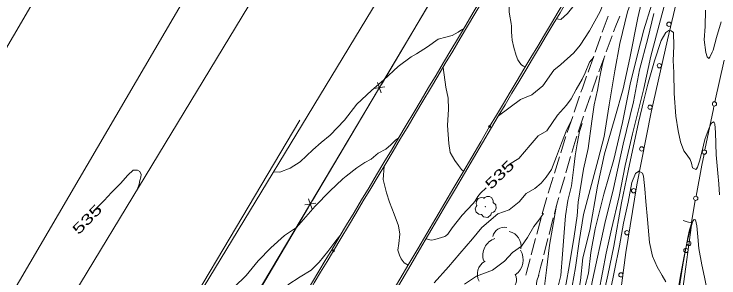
# Model space of a CAD drawing. Extents: x 2361284 to 2366480, y 6976556 to 6985346.
# Drawn here: x 2364150.7 to 2364482.3, y 6979522.2 to 6979646.3 of the extents above; entities that cross this region are included whole.
import ezdxf
from ezdxf.enums import TextEntityAlignment as Align

# ---------------------------------------------------------------- set-up
doc = ezdxf.new("R2010")
doc.units = 0
doc.header["$LTSCALE"] = 1.9
doc.header["$PDMODE"] = 32
doc.header["$PDSIZE"] = 0.95
for name, color, linetype, lineweight in [('12', 7, 'Continuous', 13), ('13', 7, 'Continuous', 13), ('16', 7, 'Continuous', 13), ('17', 7, 'Continuous', 13), ('3', 7, 'Continuous', 13), ('5', 7, 'Continuous', 13), ('6', 7, 'Continuous', 13), ('7', 7, 'Continuous', 13), ('9', 7, 'Continuous', 13)]:
    doc.layers.add(name, color=color, linetype=linetype, lineweight=lineweight)

msp = doc.modelspace()

# ---------------------------------------------------------------- linework, layer by layer
at = {"layer": '12'}
for points in [[(2364459.782, 6979662.521), (2364454.882, 6979643.634), (2364450.253, 6979626.559), (2364446.968, 6979611.337), (2364441.691, 6979589.945), (2364438.242, 6979575.132), (2364435.301, 6979560.453), (2364431.825, 6979545.209), (2364429.294, 6979533.864), (2364425.797, 6979515.601), (2364422.753, 6979501.281), (2364419.485, 6979479.998), (2364412.279, 6979443.768), (2364407.778, 6979414.374), (2364405.745, 6979397.813), (2364405.52, 6979396.2)], [(2364483.343, 6979642.624), (2364481.212, 6979635.374), (2364479.588, 6979629.428), (2364479.078, 6979628.353), (2364478.029, 6979626.133), (2364477.607, 6979625.379), (2364476.707, 6979626.241), (2364476.119, 6979628.215), (2364475.411, 6979634.299), (2364475.831, 6979640.573), (2364476.019, 6979648.135)], [(2364423.248, 6979625.932), (2364421.409, 6979623.754), (2364419.337, 6979618.684), (2364417.985, 6979615.742), (2364415.091, 6979610.854), (2364412.813, 6979606.422), (2364410.541, 6979603.44), (2364406.304, 6979598.819), (2364401.305, 6979591.371), (2364397.237, 6979589.052), (2364393.499, 6979584.638), (2364388.167, 6979578.456), (2364383.713, 6979575.723), (2364382.822, 6979574.725)], [(2364428.32, 6979625.741), (2364427.577, 6979622.942), (2364426.225, 6979616.809), (2364425.175, 6979610.5), (2364423.629, 6979603.725), (2364422.482, 6979596.003), (2364420.795, 6979583.147), (2364418.547, 6979573.394), (2364416.145, 6979557.851), (2364415.676, 6979551.406), (2364414.257, 6979541.862), (2364411.793, 6979527.548), (2364409.01, 6979511.98), (2364406.093, 6979494.782), (2364401.769, 6979467.959), (2364399.099, 6979443.792), (2364395.262, 6979421.274), (2364393.346, 6979406.126), (2364391.966, 6979391.402)], [(2364362.123, 6979572.418), (2364361.165, 6979573.259), (2364359.847, 6979575.126), (2364358.034, 6979577.509), (2364355.858, 6979581.28), (2364355.298, 6979585.494), (2364354.938, 6979589.72), (2364354.588, 6979593.907), (2364355.005, 6979601.611), (2364354.936, 6979606.802), (2364353.767, 6979611.971), (2364352.498, 6979621.238)], [(2364331.563, 6979587.998), (2364330.272, 6979587.117), (2364327.984, 6979584.805), (2364325.633, 6979582.722), (2364321.96, 6979580.987), (2364318.646, 6979578.145), (2364315.673, 6979576.446), (2364311.945, 6979574.031), (2364306.953, 6979570.033), (2364305.354, 6979568.858), (2364299.208, 6979563.029), (2364292.354, 6979556.054), (2364283.57, 6979546.02), (2364277.887, 6979542.135), (2364271.511, 6979536.375), (2364265.488, 6979530.307), (2364259.875, 6979523.373), (2364254.305, 6979517.95), (2364252.164, 6979515.9)], [(2364208.743, 6979564.099), (2364209.481, 6979566.386), (2364209.806, 6979568.039), (2364210.281, 6979569.564), (2364210.408, 6979570.915), (2364209.856, 6979572.21), (2364208.779, 6979572.95), (2364206.748, 6979572.991), (2364204.212, 6979570.566), (2364200.709, 6979566.663), (2364199.512, 6979565.361), (2364196.469, 6979562.472), (2364193.115, 6979558.71), (2364188.072, 6979553.642)], [(2364372.819, 6979564.619), (2364370.153, 6979562.034), (2364368.891, 6979560.459), (2364367.407, 6979558.191), (2364366.59, 6979557.12), (2364361.48, 6979551.671), (2364356.837, 6979545.716), (2364354.743, 6979542.789), (2364353.87, 6979542.035), (2364353.354, 6979541.763), (2364351.779, 6979541.268), (2364348.618, 6979540.238), (2364347.267, 6979540.045), (2364346.339, 6979540.117), (2364344.506, 6979540.569)]]:
    msp.add_lwpolyline(points, dxfattribs=at)
at = {"layer": '13'}
for points in [[(2364478.147, 6979741.01), (2364477.753, 6979742.517), (2364476.748, 6979743.957), (2364474.75, 6979744.828), (2364471.373, 6979744.496), (2364469.804, 6979742.251), (2364466.765, 6979737.982), (2364463.213, 6979731.787), (2364458.518, 6979721.773), (2364453.144, 6979711.7), (2364446.981, 6979700.392), (2364440.962, 6979688.704), (2364434.327, 6979676.55), (2364426.81, 6979665.688), (2364423.553, 6979662.217), (2364416.229, 6979653.157), (2364411.131, 6979646.567), (2364407.986, 6979643.828), (2364405.814, 6979644.076)], [(2364453.088, 6979688.099), (2364451.543, 6979684.404), (2364449.725, 6979677.936), (2364447.308, 6979670.234), (2364444.148, 6979660.723), (2364439.285, 6979647.366), (2364435.666, 6979632.501), (2364433.269, 6979619.576), (2364430.629, 6979603.641), (2364428.272, 6979588.707), (2364425.444, 6979577.92), (2364421.679, 6979563.754), (2364418.629, 6979552.134), (2364416.501, 6979539.353), (2364414.846, 6979527.187), (2364413.231, 6979518.321), (2364409.434, 6979491.563), (2364406.761, 6979471.848), (2364403.143, 6979452.741), (2364400.521, 6979439.316), (2364398.096, 6979426.182), (2364396.334, 6979410.595), (2364394.267, 6979394.513), (2364394.178, 6979393.382)], [(2364445.755, 6979685.269), (2364443.624, 6979682.229), (2364439.113, 6979673.905), (2364434.983, 6979664.326), (2364429.86, 6979656.117), (2364426.492, 6979647.574), (2364421.488, 6979638.486), (2364417.023, 6979631.703), (2364414.077, 6979628.065), (2364407.948, 6979622.606), (2364404.603, 6979619.924), (2364399.513, 6979612.646), (2364394.354, 6979608.347), (2364389.024, 6979606.206), (2364378.556, 6979598.425)], [(2364391.347, 6979621.698), (2364391.021, 6979621.65), (2364390.306, 6979621.854), (2364389.565, 6979622.361), (2364389.091, 6979622.809), (2364388.287, 6979623.809), (2364387.721, 6979624.814), (2364386.966, 6979626.867), (2364385.861, 6979630.567), (2364385.098, 6979634.123), (2364384.82, 6979635.917), (2364384.693, 6979637.927), (2364384.689, 6979640.62), (2364384.603, 6979641.956), (2364383.711, 6979646.346), (2364383.617, 6979647.392), (2364383.647, 6979649.509), (2364383.83, 6979652.349), (2364383.843, 6979653.763), (2364383.591, 6979655.857), (2364383.098, 6979657.633), (2364381.781, 6979661.08), (2364380.2, 6979664.646), (2364379.33, 6979666.397)], [(2364447.792, 6979660.287), (2364444.232, 6979644.522), (2364440.422, 6979625.636), (2364437.218, 6979611.254), (2364433.26, 6979597.395), (2364428.509, 6979580.65), (2364425.173, 6979565.407), (2364421.6, 6979544.762), (2364418.234, 6979531.669), (2364417.125, 6979521.038), (2364412.355, 6979493.712), (2364408.882, 6979467.517), (2364405.962, 6979449.618), (2364403.052, 6979432.78), (2364399.03, 6979412.13), (2364397.575, 6979395.785), (2364396.338, 6979381.783), (2364395.31, 6979369.972), (2364394.838, 6979359.678)], [(2364450.635, 6979650.524), (2364447.035, 6979638.999), (2364443.901, 6979626.759), (2364440.598, 6979613.347), (2364436.95, 6979595.29), (2364432.945, 6979577.901), (2364428.219, 6979561.696), (2364424.115, 6979545.256), (2364422.12, 6979534.215), (2364420.953, 6979524.425), (2364419.265, 6979517.839), (2364415.382, 6979492.941), (2364413.776, 6979481.954), (2364411.685, 6979466.343), (2364407.49, 6979444.662), (2364406.714, 6979436.855), (2364403.368, 6979422.681), (2364402.201, 6979409.91), (2364400.922, 6979398.247), (2364400.056, 6979392.508), (2364398.938, 6979381.818), (2364398.183, 6979371.85), (2364397.562, 6979359.294)], [(2364451.702, 6979646.653), (2364448.843, 6979634.936), (2364444.975, 6979620.078), (2364442.128, 6979605.001), (2364437.316, 6979585.214), (2364432.645, 6979564.218), (2364428.571, 6979547.778), (2364422.794, 6979521.192), (2364418.29, 6979497.338), (2364415.587, 6979477.671), (2364413.367, 6979465.059), (2364410.211, 6979448.738), (2364406.545, 6979428.303), (2364403.57, 6979405.733), (2364403.091, 6979399.307)], [(2364362.275, 6979639.543), (2364361.26, 6979639.014), (2364359.551, 6979637.837), (2364356.826, 6979636.231), (2364353.883, 6979635.433), (2364350.242, 6979634.489), (2364345.266, 6979630.891), (2364339.978, 6979627.571), (2364337.57, 6979626.238), (2364331.413, 6979621.658), (2364324.663, 6979615.374), (2364318.819, 6979610.399), (2364311.901, 6979603.913), (2364306.213, 6979596.377), (2364299.447, 6979589.443), (2364295.17, 6979585.993), (2364291.232, 6979582.555), (2364285.258, 6979576.787), (2364280.605, 6979573.893), (2364275.742, 6979572.046), (2364272.681, 6979572.137)], [(2364482.575, 6979561.372), (2364482.267, 6979566.5), (2364481.829, 6979571.556), (2364481.417, 6979574.922), (2364481.068, 6979580.059), (2364480.758, 6979590.567), (2364480.448, 6979594.744), (2364480.133, 6979595.281), (2364479.72, 6979595.587), (2364478.795, 6979595.078), (2364477.686, 6979592.797), (2364475.757, 6979587.38), (2364474.388, 6979582.017), (2364473.163, 6979577.224), (2364472.28, 6979574.365), (2364471.708, 6979573.59), (2364471.432, 6979573.167), (2364469.883, 6979574.042), (2364469.472, 6979576.249), (2364468.726, 6979577.942), (2364467.337, 6979579.928), (2364465.737, 6979582.064), (2364464.267, 6979586.271), (2364463.118, 6979591.369), (2364462.002, 6979598.379), (2364461.26, 6979609.023), (2364461.116, 6979618.941), (2364460.854, 6979624.449), (2364461.05, 6979631.202), (2364460.998, 6979637.622), (2364459.92, 6979638.502), (2364458.799, 6979638.631), (2364457.358, 6979637.627), (2364455.104, 6979633.986), (2364451.964, 6979624.324), (2364449.827, 6979616.714), (2364448.789, 6979613.355), (2364446.929, 6979605.917), (2364444.439, 6979595.391), (2364439.595, 6979572.674), (2364436.529, 6979557.485), (2364432.882, 6979537.199), (2364430.071, 6979523.532), (2364425.109, 6979501.713)], [(2364412.822, 6979595.981), (2364410.8, 6979592.031), (2364408.32, 6979585.559), (2364405.819, 6979579.374), (2364403.497, 6979573.271), (2364401.003, 6979569.567), (2364398.748, 6979566.876), (2364395.693, 6979564.287), (2364391.575, 6979561.917), (2364388.392, 6979557.987), (2364383.566, 6979554.311), (2364378.255, 6979552.31), (2364370.796, 6979545.989), (2364366.306, 6979540.636), (2364360.471, 6979533.699), (2364355.131, 6979527.369), (2364348.292, 6979519.874)], [(2364417.983, 6979594.88), (2364416.709, 6979591.118), (2364415.574, 6979585.238), (2364414.737, 6979579.708), (2364414.118, 6979574.292), (2364412.872, 6979565.53), (2364411.297, 6979558.696), (2364410.075, 6979551.423), (2364409.549, 6979543.607), (2364408.676, 6979533.388), (2364407.882, 6979523.291), (2364405.128, 6979512.123), (2364403.163, 6979500.015), (2364401.81, 6979491.991), (2364399.978, 6979479.582), (2364397.599, 6979462.619), (2364395.837, 6979450.202), (2364393.925, 6979433.673), (2364391.852, 6979416.022), (2364389.604, 6979398.999), (2364389.505, 6979393.668)], [(2364336.082, 6979528.178), (2364334.192, 6979529.26), (2364332.764, 6979531.127), (2364332.068, 6979532.869), (2364331.284, 6979535.302), (2364331.676, 6979538.347), (2364332.233, 6979542.832), (2364331.476, 6979546.745), (2364329.544, 6979552.157), (2364327.279, 6979557.916), (2364325.869, 6979562.183), (2364324.328, 6979568.518), (2364324.799, 6979574.803)], [(2364457.314, 6979520.35), (2364455.646, 6979523.305), (2364453.296, 6979527.383), (2364451.108, 6979532.432), (2364449.596, 6979538.948), (2364448.744, 6979549.73), (2364447.954, 6979558.134), (2364447.427, 6979564.088), (2364446.789, 6979570.153), (2364446.316, 6979571.578), (2364444.697, 6979572.443), (2364443.127, 6979571.398), (2364441.328, 6979567.111), (2364439.585, 6979557.924), (2364437.38, 6979547.972), (2364435.571, 6979537.304), (2364433.151, 6979525.711), (2364429.52, 6979507.965)], [(2364405.946, 6979556.484), (2364404.514, 6979548.3), (2364402.565, 6979537.651), (2364401.159, 6979525.807), (2364399.648, 6979513.271), (2364399.262, 6979505.527), (2364398.64, 6979494.101), (2364395.799, 6979481.643), (2364393.187, 6979464.937), (2364391.267, 6979452.378), (2364390.036, 6979439.826), (2364388.035, 6979425.105), (2364387.714, 6979414.643), (2364387.188, 6979402.716), (2364385.924, 6979389.445), (2364385.383, 6979375.808), (2364384.823, 6979366.332), (2364385.444, 6979360.999)], [(2364399.775, 6979552.525), (2364397.585, 6979549.314), (2364395.253, 6979546.392), (2364392.302, 6979541.193), (2364389.49, 6979537.176), (2364385.238, 6979534.155), (2364381.376, 6979530.149), (2364375.736, 6979525.915), (2364368.244, 6979523.024), (2364362.667, 6979519.361)], [(2364476.417, 6979517.932), (2364475.503, 6979522.623), (2364474.317, 6979528.452), (2364472.925, 6979536.06), (2364472.433, 6979541.535), (2364471.943, 6979546.781), (2364471.296, 6979549.535), (2364470.724, 6979549.779), (2364470.052, 6979548.933), (2364469.07, 6979545.993), (2364467.721, 6979540.66), (2364465.825, 6979531.732), (2364464.367, 6979524.178), (2364463.329, 6979517.648)], [(2364304.02, 6979541.954), (2364302.041, 6979539.685), (2364298.268, 6979534.658), (2364294.186, 6979529.58), (2364290.431, 6979525.934), (2364285.272, 6979522.685), (2364279.458, 6979518.949)], [(2364397.64, 6979523.533), (2364396.716, 6979520.844), (2364395.876, 6979514.476), (2364394.911, 6979506.656), (2364393.841, 6979497.186), (2364392.977, 6979490.166), (2364392.315, 6979482.03), (2364391.452, 6979473.922), (2364389.993, 6979465.337), (2364388.75, 6979457.305), (2364387.801, 6979447.546), (2364386.739, 6979437.275), (2364385.035, 6979425.057), (2364383.062, 6979412.699), (2364382.638, 6979401.643), (2364382.268, 6979393.159), (2364381.664, 6979385.194), (2364381.495, 6979376.651), (2364381.529, 6979368.881), (2364381.579, 6979361.542)]]:
    msp.add_lwpolyline(points, dxfattribs=at)
at = {"layer": '16'}
for points in [[(2364368.467, 6979556.327), (2364368.487, 6979556.338), (2364368.407, 6979556.407), (2364368.171, 6979557.035), (2364368.208, 6979558.315), (2364369.096, 6979559.614), (2364370.402, 6979560.096), (2364371.523, 6979559.907), (2364371.755, 6979559.779), (2364371.825, 6979559.779), (2364371.874, 6979559.82), (2364372.222, 6979560.113), (2364373.087, 6979560.562), (2364374.298, 6979560.493), (2364375.414, 6979559.904), (2364376.147, 6979558.481), (2364376.155, 6979557.621)], [(2364376.145, 6979557.64), (2364377.285, 6979556.581), (2364377.571, 6979554.994), (2364376.863, 6979553.667), (2364376.208, 6979553.121), (2364375.54, 6979552.904), (2364375.39, 6979552.893), (2364375.371, 6979552.783), (2364375.05, 6979551.88), (2364373.511, 6979550.715), (2364371.618, 6979550.997), (2364370.719, 6979551.939), (2364370.648, 6979552.068), (2364370.528, 6979552.047), (2364369.317, 6979552.165), (2364368.047, 6979553.163), (2364367.702, 6979554.8), (2364368.072, 6979555.824), (2364368.398, 6979556.267), (2364368.467, 6979556.317)]]:
    msp.add_lwpolyline(points, dxfattribs=at)
msp.add_circle((2364372.433, 6979555.755), 0.1, dxfattribs=at)
for centre, radius, start, end in [((2364381.342, 6979540.554), 5.525, 77.99052, 167.99052), ((2364382.275, 6979537.247), 6.914, 348.17261, 78.17261), ((2364379.514, 6979532.863), 8.292, 107.96241, 197.96241), ((2364381.959, 6979530.69), 8.292, 303.16198, 33.16198), ((2364375.538, 6979523.939), 6.914, 118.22089, 208.22089), ((2364381.53, 6979521.378), 5.525, 296.31392, 26.31392)]:
    msp.add_arc(centre, radius, start, end, dxfattribs=at)
at = {"layer": '17'}
for points in [[(2364420.68, 6979314.33), (2364420.858, 6979326.153), (2364421.256, 6979337.977), (2364421.786, 6979347.443), (2364422.336, 6979356.908), (2364424.573, 6979397.142), (2364426.831, 6979437.366), (2364429.983, 6979469.778), (2364434.286, 6979502.081), (2364438.572, 6979534.112), (2364443.618, 6979566.032), (2364450.423, 6979600.239), (2364458.1, 6979634.264), (2364467.04, 6979672.172), (2364476.622, 6979709.904), (2364482.432, 6979730.02), (2364488.2, 6979750.146), (2364489.802, 6979756.212), (2364491.375, 6979762.277), (2364492.349, 6979766.057), (2364493.313, 6979769.836)], [(2364469.628, 6979548.309), (2364468.421, 6979544.827), (2364467.655, 6979541.3), (2364465.368, 6979528.357), (2364463.321, 6979515.387), (2364460.598, 6979495.681), (2364457.936, 6979475.974), (2364455.418, 6979456.799), (2364452.96, 6979437.624), (2364451.151, 6979422.785), (2364449.382, 6979407.949), (2364448.236, 6979399.027), (2364447.321, 6979390.089), (2364447.069, 6979385.046), (2364446.857, 6979379.993), (2364446.171, 6979365.976), (2364445.504, 6979351.959), (2364444.783, 6979329.911), (2364444.353, 6979307.846)], [(2364453.304, 6979305.691), (2364453.989, 6979333.598), (2364454.945, 6979361.5), (2364455.701, 6979375.577), (2364456.507, 6979389.646), (2364456.823, 6979397.478), (2364457.098, 6979405.312), (2364457.467, 6979425.427), (2364457.846, 6979445.541), (2364459.079, 6979467.134), (2364461.385, 6979488.637), (2364464.031, 6979508.033), (2364466.717, 6979527.42), (2364468.167, 6979537.864), (2364469.628, 6979548.309)]]:
    msp.add_lwpolyline(points, dxfattribs=at)
for centre in [(2364458.793, 6979641.559), (2364454.319, 6979622.056), (2364449.914, 6979602.547), (2364445.955, 6979582.917), (2364442.165, 6979563.241), (2364439.042, 6979543.486), (2364468.169, 6979538.461), (2364466.782, 6979535.147), (2364436.166, 6979523.671)]:
    msp.add_circle(centre, 1, dxfattribs=at)
at = {"layer": '3'}
for p, q in [((2364375.258, 6979592.923), (2364375.262, 6979592.931)), ((2364300.123, 6979535.459), (2364300.123, 6979535.458))]:
    msp.add_line(p, q, dxfattribs=at)
for points in [[(2364358.602, 6979708.766), (2364374.682, 6979699.409), (2364212.068, 6979425.941), (2364174.293, 6979448.495)], [(2364285.145, 6979596.511), (2364203.707, 6979459.342), (2364160.556, 6979485.137)]]:
    msp.add_lwpolyline(points, dxfattribs=at)
for centre, radius, start, end in [((2330393.031, 6999931.453), 39602.671, 329.09927, 329.39079), ((2330393.031, 6999931.453), 39603.631, 329.09927, 329.39079), ((2338563.851, 6994972.811), 30011.124, 329.04346, 329.46126), ((2338563.851, 6994972.811), 30012.084, 329.04346, 329.46126), ((2343838.164, 6991622.203), 23799.793, 328.99957, 329.64105), ((2343838.163, 6991622.203), 23800.753, 328.99957, 329.64105), ((2377000.078, 6971906.412), 14815.236, 149.00615, 149.73404), ((2377000.078, 6971906.412), 14814.276, 149.00615, 149.73404)]:
    msp.add_arc(centre, radius, start, end, dxfattribs=at)
for p in [(2364374.434, 6979593.416), (2364300.946, 6979534.964)]:
    msp.add_point(p, dxfattribs=at)
at = {"layer": '5'}
for p, q in [((2364480.42, 6979605.025), (2364484.833, 6979624.668)), ((2364469.337, 6979548.386), (2364471.21, 6979558.675))]:
    msp.add_line(p, q, dxfattribs=at)
for points in [[(2364475.714, 6979582.409), (2364479.711, 6979601.817), (2364479.989, 6979603.081)], [(2364471.571, 6979560.629), (2364474.232, 6979575.234), (2364475.303, 6979580.405)], [(2364469.337, 6979548.187), (2364467.407, 6979548.673), (2364465.468, 6979549.162)]]:
    msp.add_lwpolyline(points, dxfattribs=at)
for centre in [(2364480.216, 6979604.069), (2364475.501, 6979581.394), (2364471.393, 6979559.66)]:
    msp.add_circle(centre, 1, dxfattribs=at)
at = {"layer": '6'}
for p, q in [((2364430.152, 6979645.398), (2364427.445, 6979637.873)), ((2364429.262, 6979628.58), (2364432.051, 6979636.076)), ((2364423.412, 6979626.564), (2364420.733, 6979619.027)), ((2364425.782, 6979619.205), (2364428.57, 6979626.703)), ((2364416.761, 6979607.7), (2364414.183, 6979600.124)), ((2364419.272, 6979600.292), (2364421.85, 6979607.868)), ((2364416.051, 6979590.821), (2364418.63, 6979598.396)), ((2364413.541, 6979598.228), (2364410.953, 6979590.653)), ((2364407.33, 6979579.218), (2364404.953, 6979571.575)), ((2364410.322, 6979571.656), (2364412.55, 6979579.338)), ((2364404.361, 6979569.669), (2364401.984, 6979562.026)), ((2364407.524, 6979562.049), (2364409.761, 6979569.731)), ((2364398.654, 6979550.504), (2364396.577, 6979542.774)), ((2364402.387, 6979542.709), (2364404.384, 6979550.459)), ((2364396.056, 6979540.839), (2364393.979, 6979533.108)), ((2364399.89, 6979533.024), (2364401.886, 6979540.774))]:
    msp.add_line(p, q, dxfattribs=at)
for points in [[(2364432.744, 6979637.953), (2364433.827, 6979640.854), (2364435.643, 6979645.41)], [(2364426.772, 6979635.986), (2364426.246, 6979634.541), (2364424.084, 6979628.45)], [(2364420.061, 6979617.141), (2364418.065, 6979611.532), (2364417.403, 6979609.596)], [(2364422.492, 6979609.764), (2364425.002, 6979617.108), (2364425.09, 6979617.328)], [(2364410.3, 6979588.757), (2364410.183, 6979588.405), (2364407.922, 6979581.125)], [(2364413.112, 6979581.264), (2364414.942, 6979587.562), (2364415.409, 6979588.925)], [(2364401.392, 6979560.121), (2364400.345, 6979556.76), (2364399.176, 6979552.439)], [(2364404.885, 6979552.393), (2364406.226, 6979557.606), (2364406.962, 6979560.124)], [(2364393.458, 6979531.174), (2364391.728, 6979524.757), (2364391.411, 6979523.444)], [(2364397.442, 6979523.331), (2364398.53, 6979527.782), (2364399.389, 6979531.09)]]:
    msp.add_lwpolyline(points, dxfattribs=at)
at = {"layer": '7'}
for points in [[(2364087.417, 6979528.354), (2364131.022, 6979502.846), (2364135.903, 6979511.193), (2364144.612, 6979506.106), (2364275.656, 6979730.424), (2364242.339, 6979749.889), (2364232.39, 6979732.853), (2364213.374, 6979743.963)], [(2364204.064, 6979458.939), (2364160.872, 6979485.119), (2364300.52, 6979715.5), (2364343.721, 6979689.309)]]:
    msp.add_lwpolyline(points, close=True, dxfattribs=at)
at = {"layer": '9'}
for p, q in [((2364325.074, 6979612.098), (2364320, 6979611.38)), ((2364323.44, 6979609.343), (2364321.633, 6979614.136)), ((2364291.05, 6979558.572), (2364321.651, 6979610.176)), ((2364290.998, 6979554.641), (2364289.193, 6979559.434)), ((2364258.6, 6979503.869), (2364289.211, 6979555.474)), ((2364292.632, 6979557.396), (2364287.559, 6979556.678))]:
    msp.add_line(p, q, dxfattribs=at)
msp.add_lwpolyline([(2364323.493, 6979613.273), (2364349.034, 6979656.348), (2364354.093, 6979664.887)], dxfattribs=at)

# ---------------------------------------------------------------- texts
at = {"layer": '12'}
for rotation, width, p in [(44.157, 1.5, (2364380.8, 6979569.113)), (45.613, 1.55, (2364186.79, 6979548.137))]:
    msp.add_text(' 535 ', height=4.8, rotation=rotation, dxfattribs=dict(at, width=width)).set_placement(p, align=Align.CENTER)

doc.saveas('drawing.dxf')
